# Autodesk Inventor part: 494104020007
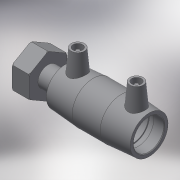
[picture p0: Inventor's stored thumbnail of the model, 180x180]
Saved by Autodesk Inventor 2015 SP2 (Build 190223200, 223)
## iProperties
Created: 2017-06
Part Number: 494104020007
Material: Generic
Description: PLASSON FEMALE FREE NUT TRANSITION COUPLER 20-3/4"
Document SubType Name: Modeling
Designer: KIM
Mass: 55.0731 g
Surface Area: 148.067 cm^2
Volume: 55.0731 cm^3
Density: 1 g/cm^3
Appearance: Default
Author: KIM
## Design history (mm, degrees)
derived "494104.ipt"
feature "Solid1::494104.ipt"
tag "TaggingFeature1"
body "Solid1"
other parameters: "d0" = 76, "d2" = 31, "d3" = 37, "d4" = 25.33333, "d5" = 27.9, "d6" = 19, "d8" = 168 deg, "d10" = 14.8, "d11" = 4.93333, "d29" = 34, "d30" = 14, "d31" = 26.6, "d34" = 5 deg, "d41" = 4, "d42" = 14, "d43" = 0, "d48" = 3, "d49" = 0, "d57" = 14, "d80" = 0.4, "d83" = 15, "d84" = 9.9, "d85" = 0.99, "d86" = 19.2936, "d87" = 24.117, "d88" = 36.1755, "d89" = 31, "d90" = 0.72351, "d94" = 0, "d95" = 0.99, "d96" = 16.8819, "L_" = 106, "L_1" = 37, "D_1" = 31, "A_" = 34, "d_2" = 12, "D_" = 14, "G_" = 24.117
